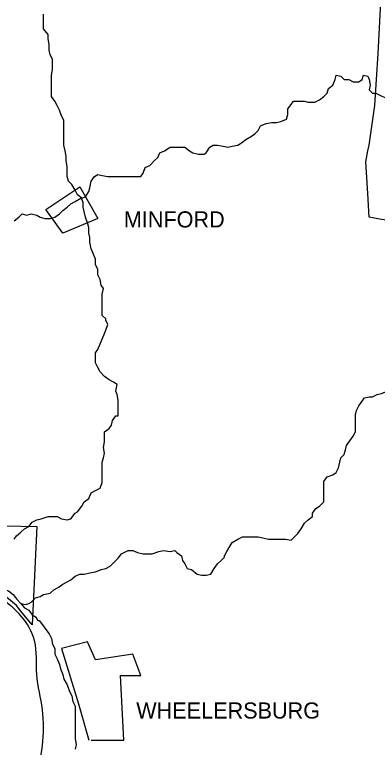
# Model space of a CAD drawing. Extents: x 0 to 34, y 0 to 22.
# Drawn here: x 6.469 to 6.907, y 16.374 to 17.259 of the extents above; entities that cross this region are included whole.
import ezdxf

# ---------------------------------------------------------------- set-up
doc = ezdxf.new("R2010")
doc.units = 0
doc.layers.add('Default', color=7, linetype='Continuous')

msp = doc.modelspace()

# ---------------------------------------------------------------- linework, layer by layer
at = {"layer": 'Default'}
for points in [[(7.28787, 16.98684), (7.17335, 16.99229), (7.067, 17.00047), (7.01382, 17.0032), (6.9702, 17.00593), (6.93475, 17.00866), (6.91157, 17.01138), (6.89657, 17.01411), (6.89521, 17.04274), (6.89248, 17.08092), (6.89521, 17.09455), (6.89657, 17.10137), (6.90339, 17.14909), (6.90748, 17.2118), (6.9102, 17.26634), (6.91566, 17.33315), (6.92248, 17.41904), (6.81749, 17.42723), (6.73296, 17.43268)], [(6.52845, 17.13136), (6.52572, 17.13682), (6.52299, 17.14363), (6.52027, 17.14909), (6.51754, 17.15454), (6.51345, 17.15999), (6.51345, 17.16545), (6.51345, 17.17227), (6.51345, 17.17908), (6.51345, 17.1859), (6.51481, 17.19272), (6.51481, 17.19817), (6.51481, 17.20499), (6.51209, 17.21044), (6.51072, 17.2159), (6.51072, 17.22271), (6.50936, 17.22953), (6.50936, 17.23498), (6.50391, 17.2418), (6.50391, 17.24589), (6.50391, 17.25407), (6.50391, 17.25952)], [(6.73841, 17.10137), (6.7425, 17.10409), (6.74796, 17.10818), (6.75477, 17.11228), (6.75887, 17.115), (6.76296, 17.11909), (6.76568, 17.12455), (6.7725, 17.12727), (6.77932, 17.12864), (6.78477, 17.12864), (6.79022, 17.13), (6.79704, 17.13273), (6.7984, 17.13818), (6.7984, 17.145), (6.80249, 17.15045), (6.80522, 17.15454), (6.81204, 17.15454), (6.81886, 17.15454), (6.82295, 17.15318), (6.83113, 17.15318), (6.83658, 17.1559), (6.84203, 17.15999), (6.84612, 17.16409), (6.84749, 17.16954), (6.85294, 17.17363), (6.85567, 17.18045), (6.85703, 17.1859), (6.86249, 17.18454), (6.86658, 17.18045), (6.87203, 17.18045), (6.87203, 17.18045), (6.87203, 17.18045)], [(6.87203, 17.18045), (6.87748, 17.17772), (6.8843, 17.17772), (6.88839, 17.18045), (6.88975, 17.1859), (6.89521, 17.18454), (6.89657, 17.18045), (6.89793, 17.17363), (6.89657, 17.16818), (6.90066, 17.16409), (6.90475, 17.16409)], [(6.90475, 17.16409), (6.9102, 17.16136), (6.91566, 17.15863), (6.92111, 17.1559), (6.92929, 17.15318), (6.93475, 17.14909), (6.93884, 17.14772), (6.94565, 17.14363), (6.95111, 17.14091), (6.95247, 17.14091), (6.95247, 17.14091)], [(6.55026, 17.03729), (6.54481, 17.04138), (6.54208, 17.04683), (6.53799, 17.05365), (6.5339, 17.05774), (6.53254, 17.06319), (6.53254, 17.07001), (6.53254, 17.07546), (6.53117, 17.08228), (6.53117, 17.08773), (6.52981, 17.09455), (6.52845, 17.10137), (6.52845, 17.10818), (6.52845, 17.115), (6.52845, 17.12046), (6.52845, 17.12727), (6.52845, 17.13136)], [(6.62116, 17.06319), (6.62389, 17.06728), (6.62661, 17.0741), (6.63207, 17.07683), (6.63752, 17.08228), (6.64161, 17.08637), (6.64434, 17.09182), (6.64979, 17.09455), (6.65661, 17.09864), (6.66206, 17.09864), (6.66752, 17.09864), (6.67433, 17.09864), (6.67979, 17.09455), (6.68388, 17.09182), (6.69069, 17.09046), (6.69751, 17.09046), (6.70024, 17.09182), (6.70433, 17.09864), (6.70842, 17.10137), (6.71387, 17.10137), (6.72069, 17.1), (6.72614, 17.09864), (6.7316, 17.1), (6.73841, 17.10137)], [(6.55026, 17.03729), (6.55435, 17.03865), (6.55844, 17.04547), (6.55981, 17.04956), (6.56117, 17.05774), (6.56526, 17.06319), (6.56935, 17.06592), (6.5748, 17.06456), (6.58162, 17.06319), (6.58707, 17.06319), (6.59389, 17.06319), (6.60071, 17.06319), (6.60753, 17.06319), (6.61434, 17.06319), (6.6198, 17.06319), (6.62116, 17.06319)], [(6.50663, 17.02365), (6.54754, 17.05092), (6.56935, 17.01275), (6.52708, 16.99502), (6.50663, 17.02365)], [(6.46846, 17.01002), (6.47391, 17.01411), (6.478, 17.0182), (6.48345, 17.01684), (6.48891, 17.0182), (6.49573, 17.01684), (6.49982, 17.01411), (6.50527, 17.01275), (6.51209, 17.01275), (6.51754, 17.01411), (6.52299, 17.0182), (6.52708, 17.02229), (6.53254, 17.02638), (6.53663, 17.03047), (6.54208, 17.0332), (6.5489, 17.03729), (6.55026, 17.03729)], [(6.57889, 16.8914), (6.5748, 16.89549), (6.5748, 16.90231), (6.5748, 16.90776), (6.5748, 16.91594), (6.5748, 16.9214), (6.57617, 16.92821), (6.57344, 16.9323), (6.57208, 16.93912), (6.56935, 16.94457), (6.56935, 16.95139), (6.56662, 16.95685), (6.56662, 16.96366), (6.5639, 16.97048), (6.56117, 16.97593), (6.55981, 16.98411), (6.55981, 16.98957), (6.55844, 16.99502), (6.55844, 17.00184), (6.55708, 17.00729), (6.55435, 17.01411), (6.55299, 17.02093), (6.55163, 17.02638), (6.55163, 17.03183), (6.55026, 17.03592), (6.55026, 17.03729)], [(6.59389, 16.77415), (6.59389, 16.78096), (6.59389, 16.78642), (6.59389, 16.79323), (6.59253, 16.80005), (6.59116, 16.80414), (6.59253, 16.81232), (6.58844, 16.81505), (6.58298, 16.81778), (6.57753, 16.82187), (6.57208, 16.82732), (6.56935, 16.83277), (6.56662, 16.83823), (6.56662, 16.84368), (6.56662, 16.8505), (6.56935, 16.85459), (6.57208, 16.86141), (6.5748, 16.86686), (6.57753, 16.87368), (6.57889, 16.87777), (6.58162, 16.88458), (6.57889, 16.89004), (6.57889, 16.8914)], [(6.90066, 16.79733), (6.90611, 16.80005), (6.91157, 16.80142), (6.91839, 16.80414), (6.92111, 16.8096), (6.92793, 16.81369), (6.93202, 16.81778), (6.93747, 16.82187), (6.94293, 16.82459), (6.94838, 16.82459), (6.9552, 16.82732), (6.95929, 16.82868), (6.96611, 16.83277), (6.97156, 16.8355), (6.97838, 16.83686), (6.98383, 16.83414), (6.99065, 16.83277), (6.9961, 16.83277), (7.00292, 16.82868), (7.00837, 16.82732), (7.01382, 16.82323), (7.01519, 16.82187), (7.01655, 16.82187)], [(6.8284, 16.65689), (6.83249, 16.66235), (6.83658, 16.66507), (6.84203, 16.67053), (6.84203, 16.67734), (6.84203, 16.6828), (6.84203, 16.68961), (6.84203, 16.69507), (6.84612, 16.70052), (6.85294, 16.70325), (6.85703, 16.70598), (6.85976, 16.71143), (6.86112, 16.71825), (6.86249, 16.7237), (6.86658, 16.72779), (6.86794, 16.73324), (6.8693, 16.7387), (6.87339, 16.74415), (6.87748, 16.74961), (6.88021, 16.75506), (6.88021, 16.76324), (6.88021, 16.76869), (6.88021, 16.77551), (6.88157, 16.78096), (6.8843, 16.78642), (6.88839, 16.79187), (6.89112, 16.79596), (6.89657, 16.79733), (6.90066, 16.79733)], [(6.53663, 16.65008), (6.54208, 16.65689), (6.54481, 16.65826), (6.55026, 16.66507), (6.55299, 16.67053), (6.55844, 16.67462), (6.56117, 16.68143), (6.56662, 16.68416), (6.57208, 16.68689), (6.5748, 16.69371), (6.5748, 16.69916), (6.5748, 16.70598), (6.5748, 16.71143), (6.5748, 16.71825), (6.57617, 16.7237), (6.57753, 16.72915), (6.57617, 16.73597), (6.57753, 16.74279), (6.57753, 16.74824), (6.57753, 16.75506), (6.58298, 16.75915), (6.58571, 16.76324), (6.58707, 16.76869), (6.59116, 16.77415), (6.59389, 16.77415), (6.59389, 16.77415)], [(6.72205, 16.60508), (6.72478, 16.61054), (6.72887, 16.61735), (6.7316, 16.62144), (6.73841, 16.62553), (6.74387, 16.62826), (6.74932, 16.62826), (6.75614, 16.62826), (6.76296, 16.62826), (6.76841, 16.6269), (6.77523, 16.62553), (6.78204, 16.62553), (6.79022, 16.62553), (6.79568, 16.62553), (6.80249, 16.62417), (6.80658, 16.62826), (6.81068, 16.63235), (6.81477, 16.6378), (6.81886, 16.64462), (6.82295, 16.64871), (6.8284, 16.6528), (6.8284, 16.65553), (6.8284, 16.65689)], [(6.24213, 16.64599), (6.49573, 16.64053), (6.49027, 16.52191), (6.47664, 16.53828), (6.47118, 16.54509), (6.44937, 16.56282)], [(6.46846, 16.62553), (6.47118, 16.62962), (6.47664, 16.63371), (6.48073, 16.6378), (6.48618, 16.64053), (6.49027, 16.64599), (6.49573, 16.64871), (6.50118, 16.65008), (6.50936, 16.6528), (6.51481, 16.6528), (6.52027, 16.6528), (6.52572, 16.65008), (6.53254, 16.64871), (6.53663, 16.65008), (6.53663, 16.65008)], [(6.48891, 16.54918), (6.49436, 16.55464), (6.49982, 16.556), (6.50391, 16.55873), (6.51209, 16.56009), (6.51618, 16.56418), (6.52163, 16.56691), (6.52708, 16.571), (6.53254, 16.57372), (6.53663, 16.57645), (6.54208, 16.58054), (6.54754, 16.58327), (6.55299, 16.58327), (6.55981, 16.58463), (6.56662, 16.58599), (6.57344, 16.58872), (6.57889, 16.59009), (6.58435, 16.59281), (6.58844, 16.5969), (6.59389, 16.60236), (6.59798, 16.60781), (6.60616, 16.6119), (6.60616, 16.6119)], [(6.60616, 16.6119), (6.61162, 16.6119), (6.61707, 16.60917), (6.62389, 16.60781), (6.62934, 16.60781), (6.63479, 16.60781), (6.64297, 16.61054), (6.64843, 16.6119), (6.65661, 16.61054), (6.66206, 16.6119), (6.66479, 16.60917), (6.67024, 16.60508), (6.67161, 16.59963), (6.67433, 16.59554), (6.67706, 16.59009), (6.68251, 16.58872), (6.68933, 16.58327), (6.69478, 16.5819), (6.70024, 16.5819), (6.70569, 16.58327), (6.70978, 16.59009), (6.71387, 16.59554), (6.71796, 16.59963), (6.72205, 16.60372), (6.72205, 16.60372), (6.72205, 16.60508)], [(6.40165, 16.571), (6.4071, 16.57236), (6.41392, 16.57372), (6.41937, 16.57372), (6.42755, 16.57372), (6.43164, 16.57236), (6.43846, 16.57236), (6.44392, 16.571), (6.45073, 16.56691), (6.45482, 16.56554), (6.46164, 16.56282), (6.46709, 16.55873), (6.47118, 16.55327), (6.47664, 16.54782), (6.47664, 16.54782)], [(6.47664, 16.54782), (6.48209, 16.54646), (6.48618, 16.54782), (6.48891, 16.54918)], [(6.47664, 16.54782), (6.48073, 16.54237), (6.48618, 16.53964), (6.49027, 16.53418), (6.49436, 16.53146), (6.49709, 16.52737), (6.49845, 16.52737)], [(6.49845, 16.52737), (6.50254, 16.52191), (6.50663, 16.51646), (6.51072, 16.51101), (6.51345, 16.50555), (6.51481, 16.49874), (6.51754, 16.49328), (6.51754, 16.48647), (6.52027, 16.48101), (6.52299, 16.47419), (6.52436, 16.46874), (6.52708, 16.46192), (6.52845, 16.45647), (6.53254, 16.44965), (6.53526, 16.44147)], [(6.56117, 16.38285), (6.60071, 16.38285), (6.59662, 16.46056), (6.62116, 16.46056), (6.61162, 16.48647), (6.56662, 16.47965), (6.55708, 16.50146), (6.52572, 16.49328), (6.54617, 16.42647), (6.55844, 16.38285)], [(6.53526, 16.44147), (6.53799, 16.43602), (6.53935, 16.4292), (6.54208, 16.42375), (6.54208, 16.41693), (6.54208, 16.41148), (6.54208, 16.40466), (6.54208, 16.39784), (6.54208, 16.39239), (6.54208, 16.38421), (6.54344, 16.37739), (6.54208, 16.37194)]]:
    msp.add_lwpolyline(points, dxfattribs=at)
msp.add_spline([(6.69478, 15.72431), (6.66479, 15.7434), (6.64025, 15.76249), (6.60889, 15.78703), (6.58844, 15.82384), (6.5748, 15.85929), (6.56253, 15.89065), (6.55299, 15.93701), (6.54754, 15.97655), (6.54754, 16.01881), (6.54754, 16.05699), (6.54481, 16.1088), (6.53117, 16.1497), (6.52027, 16.18379), (6.50391, 16.20969), (6.48754, 16.22878), (6.47936, 16.25605), (6.47936, 16.29831), (6.493, 16.33376), (6.50254, 16.37603), (6.50254, 16.41966), (6.49573, 16.46192), (6.493, 16.50283), (6.47664, 16.53282), (6.45891, 16.54918), (6.43164, 16.56418), (6.41528, 16.56691), (6.38938, 16.55873), (6.37574, 16.556), (6.3403, 16.54646), (6.30348, 16.53828), (6.2694, 16.52191), (6.24213, 16.50283), (6.21622, 16.48647), (6.18487, 16.46874), (6.15896, 16.45374), (6.13987, 16.44284), (6.11669, 16.43466), (6.08125, 16.43602), (6.04716, 16.44284), (6.01307, 16.44556), (5.9749, 16.45238), (5.94899, 16.43466), (5.92582, 16.41693), (5.90673, 16.37603), (5.889, 16.35149), (5.86582, 16.31604), (5.84674, 16.28195), (5.82356, 16.27241), (5.78402, 16.25605), (5.7513, 16.23969), (5.71039, 16.22742), (5.68313, 16.21242), (5.64631, 16.19606), (5.6245, 16.16606), (5.61223, 16.14152), (5.59859, 16.10607), (5.58905, 16.07199), (5.58632, 16.03108), (5.55496, 16.00245), (5.52088, 15.97655), (5.47316, 15.95337), (5.42271, 15.95337), (5.38181, 15.94519), (5.33682, 15.94519), (5.29319, 15.95064), (5.25229, 15.96973), (5.22638, 15.98745), (5.19229, 15.99427), (5.16639, 15.99563), (5.14867, 15.97927), (5.11458, 15.96837), (5.0914, 15.95064)], degree=3, dxfattribs=at)

# ---------------------------------------------------------------- texts
for s, height, p in [('MINFORD', 0.019502, (6.60071, 17.00184)), ('WHEELERSBURG', 0.0195024, (6.61571, 16.40875))]:
    msp.add_text(s, height=height, dxfattribs=at).set_placement(p)

doc.saveas('drawing.dxf')
